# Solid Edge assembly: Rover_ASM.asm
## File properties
Author: KULL
Template: Iso Metric Assembly.asm
Last saved by: KULL
Revision: 22
Application: Solid Edge
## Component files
la.par
hendus vidin.par
66tshoovakinnituspolt.par
66tshoova_Tagumine_kinnituspolt.par
Backsteering_1.par
brakewheel.par
Amort_vedru_ASM_SYNC.asm
VelgKorkASM_mir3.asm
Backsteering_1_mir2.par
Tagumine66tshoob_1_mir2.par
Tagumine66tshoob_2_mir2.par
reguleerimismutter_mir2.par
Amort_vedru_ASM_SYNC_mir2.asm
brakewheel_mir3.par
Chassy_1.par
imu_1.par
Tagumine66tshoob_1.par
brakewheel_mir.par
Amort_vedru_ASM_SYNC_mir.asm
Rooli otsad_mir.par
VelgKorkASM_mir.asm
Auto_kere_2.par
Rooli otsad.par
Tagumine66tshoob_2 regulaator ots.par
Tagumine66tshoob_2.par
reguleerimismutter.par
imu silindri varras.par
VelgKorkASM.asm
imu kinnitus polt.par
imu silinder.par
66tshoob esi.par
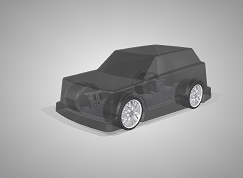
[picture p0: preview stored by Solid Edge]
